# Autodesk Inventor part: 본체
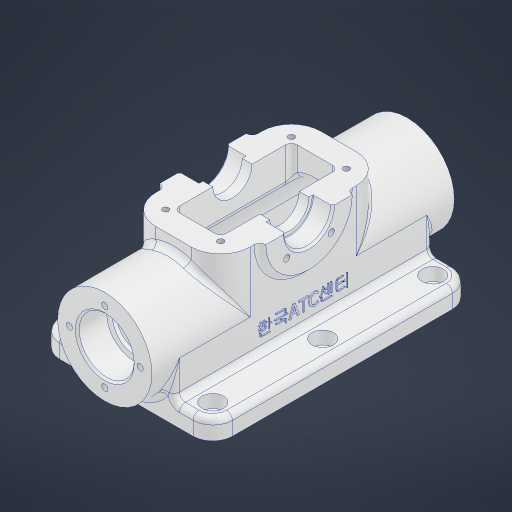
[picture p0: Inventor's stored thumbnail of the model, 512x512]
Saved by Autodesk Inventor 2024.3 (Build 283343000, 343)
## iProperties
Created: 2024-06
Part Number: 본체
Material: 알루미늄 6061
Document SubType Name: Modeling
Designer: MyPc
Density: 2.7 g/cm^3
Appearance: 알루미늄 - 평지
Mass: 551.546 g
Surface Area: 612.212 cm^2
Volume: 204.276 cm^3
Author: MyPc
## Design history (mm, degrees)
sketch "스케치1"
  geometry: L1 (-44, 66)-(44, 66); L2 (44, 66)-(44, -66); L3 (44, -66)-(-44, -66); L4 (-44, -66)-(-44, 66); L5 (-44, 66)-(44, -66); L6 (44, 66)-(-44, -66); 1 further point
  constraints: 12 end point, 2 midpoint, 2 parallel, 1 horizontal, 1 perpendicular
  dimensions: "d0" = 132 distance of L1.end L2.end; "d1" = 88 distance of L2.end L3.end
extrude "돌출1" new body sketch "스케치1" distance "d2" = 10; taper "d3" = 0 deg
sketch "스케치2"
  geometry: L1 (52, 77)-(28, 77); L2 (28, 77)-(28, -77); L3 (28, -77)-(52, -77); L4 (52, -77)-(52, 77); L5 (0, -66)-(0, 66) reference; 3 further points
  constraints: 8 end point, 2 midpoint, 2 parallel, 1 horizontal, 1 horizontal alignment, 1 perpendicular
  dimensions: "d4" = 28 distance between parallel lines of L5 L2; "d5" = 48 diameter of L4 L2; "d6" = 154 distance of L3.end L1.start
revolve "회전1" sketch "스케치2" stored, may be unused: angle "d7" = 90 deg
sketch "스케치7"
  geometry: L1 (-24, -77)-(-24, 77) reference; L2 (-44, -66)-(-15.875, -66) reference; L3 (24, -77)-(24, 77) reference; L4 (15.875, -66)-(44, -66) reference; L5 (44, 66)-(15.875, 66) reference; L6 (-15.875, 66)-(-44, 66) reference; L7 (24, -66)-(-24, -66); L8 (-24, -66)-(-24, 66); L9 (-24, 66)-(24, 66); L10 (24, 66)-(24, -66); 7 further points
  constraints: 8 end point, 4 point on line, 2 parallel, 1 horizontal, 1 perpendicular
extrude "돌출2" join sketch "스케치7" stored distance "d20" = 10; taper "d21" = 0 deg
sketch "스케치3"
  geometry: L1 (4, -77)-(52, -77) reference; L2 (4, 77)-(52, 77) reference; L3 (28, -66)-(28, -66) reference; L4 (28, 66)-(28, 66) reference; L5 (42, 77)-(42, 62); L6 (42, 62)-(39, 62); L7 (39, 62)-(39, 60); L8 (39, 60)-(46, 60); L9 (46, 60)-(46, -60); L10 (46, -60)-(39, -60); L11 (39, -60)-(39, -62); L12 (39, -62)-(42, -62); L13 (42, -62)-(42, -77); L14 (28, 77)-(28, -77); L15 (0, -66)-(0, 66) reference; L16 (52, 77)-(52, -77) reference; L17 (0, 66)-(10, 66) reference; L18 (0, -66)-(10, -66) reference; L19 (28, 66)-(28, -66) reference; L20 (28, 66)-(28, -66) reference; 3 further points
  constraints: 20 end point, 6 perpendicular, 6 point on line, 2 midpoint, 2 vertical
  dimensions: "d8" = 28 distance between parallel lines of L14 L15; "d9" = 28 diameter of L5 L14; "d10" = 22 diameter of L7 L14; "d11" = 6 distance between parallel lines of L16 L9; "d12" = 15 distance of L12.end L13.end; "d13" = 15 distance of L5.start L5.end; "d14" = 6 distance between parallel lines of L8 L17; "d15" = 6 distance between parallel lines of L10 L18
revolve "회전2" sketch "스케치3" stored, may be unused: angle "d16" = 90 deg
sketch "스케치6"
  geometry: L1 (-18, 60)-(18, 60); L2 (18, 60)-(18, -60); L3 (18, -60)-(-18, -60); L4 (-18, -60)-(-18, 60); L5 (-18, 60)-(18, -60); L6 (18, 60)-(-18, -60); 1 further point
  constraints: 12 end point, 2 midpoint, 2 parallel, 1 horizontal, 1 perpendicular
  dimensions: "d18" = 120 distance of L1.end L2.end; "d19" = 36 distance of L2.end L3.end
extrude "돌출3" cut sketch "스케치6" stored distance "d22" = 10; taper "d23" = 0 deg
node "작업 평면1"
sketch "스케치8"
  geometry: L1 (24, 66)-(24, -66) reference; L2 (24, 66)-(-24, 66) reference; L3 (-24, 66)-(-24, -66) reference; L4 (24, -66)-(-24, -66) reference; L5 (-24, 77)-(24, 77) reference; L6 (-24, -77)-(24, -77) reference; L7 (-24, 42)-(24, 42); L8 (24, 42)-(24, -42); L9 (24, -42)-(-24, -42); L10 (-24, -42)-(-24, 42); L11 (-24, 42)-(24, -42); L12 (24, 42)-(-24, -42); 4 further points
  constraints: 12 end point, 2 midpoint, 2 parallel, 1 horizontal, 1 perpendicular, 1 point on line
  dimensions: "d25" = 84 distance between parallel lines of L7 L9
extrude "돌출4" join sketch "스케치8" stored distance "d26" = 10; taper "d27" = 0 deg
fillet "모깎기1" dims "d28" = 15
sketch "스케치9"
  geometry: L1 (-9, -42)-(9, -42) reference; L2 (24, -27)-(24, 27) reference; L3 (9, 42)-(-9, 42) reference; L4 (-24, 27)-(-24, -27) reference; L5 (12, -30)-(-12, -30); L6 (-12, -30)-(-12, 30); L7 (-12, 30)-(12, 30); L8 (12, 30)-(12, -30); L9 (12, -30)-(-12, 30); L10 (-12, -30)-(12, 30); A1 r 15 centre (-9, -27) between (-24, -27) and (-9, -42) reference; A2 r 15 centre (9, -27) between (9, -42) and (24, -27) reference; A3 r 15 centre (9, 27) between (24, 27) and (9, 42) reference; A4 r 15 centre (-9, 27) between (-9, 42) and (-24, 27) reference; 1 further point
  constraints: 12 end point, 2 midpoint, 2 parallel, 1 horizontal, 1 perpendicular
  dimensions: "d29" = 60 distance of L5.end L6.end; "d30" = 24 distance of L6.end L7.end
extrude "돌출5" cut sketch "스케치9" extent not by distance; stored distance "d31" = 0; taper "d32" = 0 deg
sketch "스케치10"
  geometry: L1 (14, -32)-(-14, -32); L2 (-14, -32)-(-14, 32); L3 (-14, 32)-(14, 32); L4 (14, 32)-(14, -32); L5 (14, -32)-(-14, 32); L6 (-14, -32)-(14, 32); 5 further points
  constraints: 12 end point, 4 coincident, 2 midpoint, 2 parallel, 1 horizontal, 1 perpendicular
  dimensions: "d33" = 64 distance of L1.end L2.end; "d34" = 28 distance of L2.end L3.end
hole "구멍1" sketch "스케치10" at (-14, -32), (14, -32), (14, 32), (-14, 32) diameter "d35" = 3.242; stored, may be unused: countersink angle "d39" = 90 deg, drill point angle "d41" = 118 deg; dims "d36" = 8, "d37" = 4, "d38" = 2, "d40" = 10
node "작업 평면2"
sketch "스케치11"
  geometry: L1 (59, 27)-(59, -27) reference; C1 r 22 at (59, 0); 3 further points
  constraints: 1 centre point, 1 midpoint
  dimensions: "d43" = 44 diameter of C1
extrude "돌출6" join sketch "스케치11" stored distance "d44" = 10; taper "d45" = 0 deg
sketch "스케치12"
  geometry: A1 r 22 centre (0, 59) between (-22, 59) and (22, 59) reference; 2 further points
  constraints: 1 coincident
hole "구멍2" sketch "스케치12" at (0, 59) diameter "d46" = 20; stored, may be unused: countersink angle "d50" = 90 deg, drill point angle "d52" = 0 deg; dims "d47" = 8, "d48" = 24, "d49" = 10, "d51" = 10
sketch "스케치13"
  geometry: L1 (0, 59)-(0, 43); L2 (0, 59)-(-11.314, 47.686); L3 (0, 59)-(11.314, 47.686); A1 r 10 centre (0, 59) between (-10, 59) and (10, 59) reference; A2 r 16 centre (0, 59) between (0, 43) and (-11.314, 47.686); 3 further points
  constraints: 6 end point, 3 coincident, 3 point on circle, 1 centre point, 1 vertical, 1 other
  dimensions: "d53" = 32 diameter of A2; "d55" = 45 deg angle of L1 L2
hole "구멍3" sketch "스케치13" at (-11.314, 47.686), (11.314, 47.686) diameter "d56" = 3.242; stored, may be unused: countersink angle "d60" = 90 deg, drill point angle "d62" = 118 deg; dims "d57" = 8, "d58" = 24, "d59" = 10, "d61" = 10
sketch "스케치14" dims "d63" = 36
  geometry: L1 (0, 0)-(0, 18); C1 r 14 at (0, 0) reference; 2 further points
  constraints: 2 coincident, 2 end point, 1 vertical, 1 vertical alignment, 2 other
hole "구멍4" sketch "스케치14" at (0, 18) diameter "d64" = 3.242; stored, may be unused: countersink angle "d68" = 90 deg, drill point angle "d70" = 118 deg; dims "d65" = 8, "d66" = 4, "d67" = 2, "d69" = 10
fillet "모깎기2" dims "d74" = 10
sketch "스케치15"
  geometry: L1 (34, 56)-(-34, 56); L2 (-34, 56)-(-34, -56); L3 (-34, -56)-(34, -56); L4 (34, -56)-(34, 56); L5 (34, 56)-(-34, -56); L6 (-34, 56)-(34, -56); 7 further points
  constraints: 12 end point, 4 coincident, 4 midpoint, 2 parallel, 1 horizontal, 1 perpendicular
  dimensions: "d75" = 112 distance of L3.end L1.start; "d76" = 68 distance of L1.start L1.end
hole "구멍5" sketch "스케치15" at (34, 56), (-34, 56), (-34, -56), (34, -56), (34, 0), (-34, 0) diameter "d77" = 6.6; stored, may be unused: countersink angle "d81" = 90 deg, drill point angle "d83" = 0 deg; dims "d78" = 8, "d79" = 11, "d80" = 6.6, "d82" = 10
chamfer "모따기1" distance "d84" = 1; stored, may be unused: second distance "d85" = 2, angle "d86" = 45 deg
fillet "모깎기3" dims "d87" = 0.3
fillet "모깎기4" dims "d88" = 3
fillet "모깎기5" dims "d89" = 3
fillet "모깎기6" dims "d90" = 3
fillet "모깎기7" dims "d91" = 3
fillet "모깎기8" dims "d92" = 3
sketch "스케치16" dims "d0" = 132, "d1" = 88
  geometry: L1 (-29, -28)-(83, -28) reference; 3 further points
  constraints: 1 midpoint, 1 vertical alignment, 1 other
  dimensions: "d93" = 20 distance from line of point (27, -8) L1
feature "엠보싱1" sketch "스케치16" dims "d0" = 132, "d1" = 88, "d6" = 154, "d94" = 0.5, "d95" = 0
node "솔리드1"
mirror "미러1"
pattern_circular "원형 패턴1" dims angle "d72" = 360 deg
mirror "미러2"
node "투영된 루프1"
node "투영된 루프3"
node "투영된 루프4"
feature "A9D066F2-1C7D-4E18-AEED-F7BC21143FA4" dims "d35" = 3.242, "d36" = 8, "d37" = 4, "d38" = 2, "d39" = 90 deg, "d40" = 10, "d41" = 118 deg
other parameters: "d24" = 59, "d42" = 27
